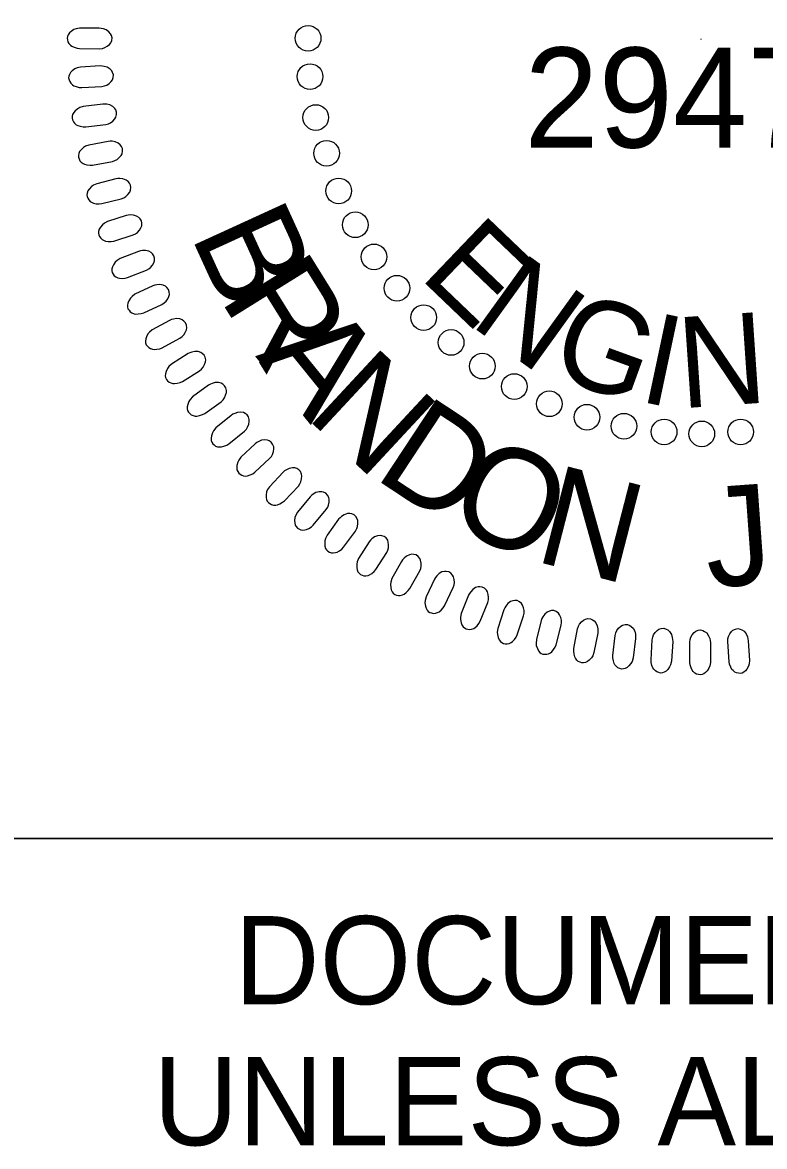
# Model space of a CAD drawing. Extents: x 505602 to 507286, y 483109 to 484209.
# Drawn here: x 507076.9 to 507123.2, y 484026.9 to 484097.1 of the extents above; entities that cross this region are included whole.
import ezdxf

# ---------------------------------------------------------------- set-up
doc = ezdxf.new("R2010")
doc.units = 0
for name, color, linetype in [('Sheet PE Seal Cell', 7, 'Continuous'), ('Sheet Profile CELL', 7, 'Continuous'), ('Sheet Sticker Exception Certification CELL', 7, 'Continuous')]:
    doc.layers.add(name, color=color, linetype=linetype)

msp = doc.modelspace()

# ---------------------------------------------------------------- linework, layer by layer
at = {"layer": 'Sheet PE Seal Cell'}
msp.add_line((507119.206, 484096.054), (507119.206, 484096.007), dxfattribs=at)
for points in [[(507081.659, 484096.717), (507080.432, 484096.717), (507080.213, 484096.679), (507080.073, 484096.628), (507079.904, 484096.516), (507079.794, 484096.418), (507079.714, 484096.306), (507079.674, 484096.202), (507079.654, 484096.089), (507079.674, 484095.978), (507079.704, 484095.858), (507079.763, 484095.753), (507079.864, 484095.649), (507079.943, 484095.589), (507080.093, 484095.521), (507080.273, 484095.462), (507080.432, 484095.439), (507081.689, 484095.431), (507081.858, 484095.453), (507081.998, 484095.499), (507082.157, 484095.588), (507082.297, 484095.7), (507082.377, 484095.797), (507082.437, 484095.954), (507082.457, 484096.104), (507082.416, 484096.253), (507082.367, 484096.358), (507082.268, 484096.485), (507082.098, 484096.605), (507081.918, 484096.672), (507081.789, 484096.702)], [(507081.712, 484094.359), (507080.487, 484094.283), (507080.271, 484094.232), (507080.134, 484094.171), (507079.972, 484094.048), (507079.868, 484093.944), (507079.796, 484093.827), (507079.763, 484093.721), (507079.75, 484093.607), (507079.777, 484093.497), (507079.815, 484093.379), (507079.88, 484093.279), (507079.987, 484093.18), (507080.07, 484093.126), (507080.223, 484093.068), (507080.406, 484093.019), (507080.566, 484093.007), (507081.822, 484093.078), (507081.99, 484093.111), (507082.126, 484093.165), (507082.279, 484093.265), (507082.412, 484093.385), (507082.486, 484093.486), (507082.536, 484093.647), (507082.546, 484093.797), (507082.497, 484093.944), (507082.44, 484094.046), (507082.333, 484094.166), (507082.157, 484094.275), (507081.973, 484094.331), (507081.842, 484094.353)], [(507081.876, 484091.978), (507080.659, 484091.825), (507080.446, 484091.76), (507080.314, 484091.691), (507080.16, 484091.559), (507080.063, 484091.448), (507079.998, 484091.327), (507079.972, 484091.218), (507079.966, 484091.104), (507080, 484090.996), (507080.044, 484090.881), (507080.116, 484090.784), (507080.229, 484090.693), (507080.316, 484090.644), (507080.472, 484090.596), (507080.658, 484090.559), (507080.819, 484090.557), (507082.067, 484090.706), (507082.232, 484090.749), (507082.365, 484090.812), (507082.512, 484090.92), (507082.636, 484091.049), (507082.704, 484091.155), (507082.743, 484091.319), (507082.744, 484091.47), (507082.686, 484091.613), (507082.623, 484091.711), (507082.509, 484091.825), (507082.326, 484091.922), (507082.139, 484091.966), (507082.007, 484091.979)], [(507082.21, 484089.653), (507081.004, 484089.423), (507080.796, 484089.345), (507080.669, 484089.269), (507080.523, 484089.126), (507080.433, 484089.01), (507080.376, 484088.885), (507080.356, 484088.775), (507080.358, 484088.661), (507080.398, 484088.555), (507080.45, 484088.443), (507080.528, 484088.351), (507080.646, 484088.267), (507080.735, 484088.223), (507080.895, 484088.185), (507081.083, 484088.16), (507081.243, 484088.167), (507082.479, 484088.395), (507082.642, 484088.449), (507082.771, 484088.519), (507082.91, 484088.637), (507083.027, 484088.774), (507083.087, 484088.884), (507083.116, 484089.049), (507083.108, 484089.2), (507083.041, 484089.339), (507082.972, 484089.433), (507082.85, 484089.539), (507082.662, 484089.625), (507082.472, 484089.657), (507082.34, 484089.662)], [(507082.689, 484087.312), (507081.501, 484087.007), (507081.298, 484086.916), (507081.175, 484086.831), (507081.039, 484086.68), (507080.957, 484086.559), (507080.907, 484086.43), (507080.895, 484086.319), (507080.903, 484086.205), (507080.95, 484086.102), (507081.009, 484085.994), (507081.093, 484085.907), (507081.216, 484085.831), (507081.308, 484085.792), (507081.469, 484085.764), (507081.658, 484085.751), (507081.818, 484085.769), (507083.037, 484086.073), (507083.196, 484086.137), (507083.32, 484086.216), (507083.452, 484086.342), (507083.56, 484086.485), (507083.613, 484086.599), (507083.632, 484086.766), (507083.614, 484086.916), (507083.538, 484087.051), (507083.464, 484087.14), (507083.336, 484087.239), (507083.142, 484087.312), (507082.951, 484087.333), (507082.818, 484087.329)], [(507083.343, 484085.028), (507082.176, 484084.649), (507081.979, 484084.546), (507081.862, 484084.454), (507081.735, 484084.294), (507081.661, 484084.167), (507081.62, 484084.036), (507081.615, 484083.925), (507081.63, 484083.812), (507081.684, 484083.712), (507081.749, 484083.607), (507081.838, 484083.526), (507081.966, 484083.458), (507082.059, 484083.424), (507082.223, 484083.407), (507082.412, 484083.406), (507082.571, 484083.433), (507083.768, 484083.814), (507083.922, 484083.888), (507084.042, 484083.974), (507084.165, 484084.108), (507084.263, 484084.258), (507084.31, 484084.375), (507084.318, 484084.543), (507084.291, 484084.691), (507084.207, 484084.821), (507084.127, 484084.905), (507083.993, 484084.995), (507083.795, 484085.057), (507083.603, 484085.065), (507083.471, 484085.053)], [(507084.102, 484082.79), (507082.961, 484082.34), (507082.77, 484082.224), (507082.659, 484082.124), (507082.543, 484081.957), (507082.477, 484081.826), (507082.444, 484081.693), (507082.446, 484081.581), (507082.468, 484081.469), (507082.528, 484081.373), (507082.6, 484081.272), (507082.693, 484081.197), (507082.825, 484081.137), (507082.921, 484081.11), (507083.086, 484081.103), (507083.274, 484081.113), (507083.431, 484081.151), (507084.602, 484081.606), (507084.752, 484081.689), (507084.865, 484081.782), (507084.98, 484081.924), (507085.069, 484082.08), (507085.108, 484082.2), (507085.105, 484082.368), (507085.069, 484082.515), (507084.977, 484082.638), (507084.892, 484082.717), (507084.753, 484082.799), (507084.551, 484082.847), (507084.359, 484082.844), (507084.228, 484082.824)], [(507085.001, 484080.631), (507083.891, 484080.109), (507083.709, 484079.982), (507083.604, 484079.875), (507083.499, 484079.701), (507083.441, 484079.567), (507083.416, 484079.431), (507083.425, 484079.32), (507083.454, 484079.21), (507083.52, 484079.117), (507083.598, 484079.021), (507083.697, 484078.952), (507083.832, 484078.9), (507083.929, 484078.88), (507084.093, 484078.882), (507084.281, 484078.905), (507084.435, 484078.952), (507085.576, 484079.48), (507085.719, 484079.573), (507085.827, 484079.673), (507085.932, 484079.821), (507086.012, 484079.982), (507086.043, 484080.105), (507086.03, 484080.272), (507085.984, 484080.416), (507085.884, 484080.534), (507085.794, 484080.608), (507085.651, 484080.681), (507085.446, 484080.716), (507085.255, 484080.701), (507085.125, 484080.673)], [(507086.049, 484078.482), (507084.973, 484077.892), (507084.799, 484077.754), (507084.702, 484077.64), (507084.607, 484077.461), (507084.558, 484077.322), (507084.542, 484077.186), (507084.557, 484077.075), (507084.594, 484076.967), (507084.666, 484076.879), (507084.75, 484076.788), (507084.852, 484076.725), (507084.99, 484076.682), (507085.089, 484076.667), (507085.252, 484076.68), (507085.438, 484076.715), (507085.589, 484076.771), (507086.694, 484077.37), (507086.832, 484077.472), (507086.932, 484077.578), (507087.029, 484077.733), (507087.097, 484077.898), (507087.121, 484078.023), (507087.097, 484078.189), (507087.043, 484078.33), (507086.936, 484078.441), (507086.842, 484078.509), (507086.693, 484078.572), (507086.487, 484078.595), (507086.297, 484078.568), (507086.169, 484078.532)], [(507087.205, 484076.408), (507086.169, 484075.75), (507086.003, 484075.602), (507085.914, 484075.483), (507085.83, 484075.297), (507085.79, 484075.157), (507085.783, 484075.019), (507085.805, 484074.909), (507085.848, 484074.804), (507085.926, 484074.72), (507086.015, 484074.635), (507086.121, 484074.579), (507086.261, 484074.544), (507086.36, 484074.536), (507086.523, 484074.559), (507086.707, 484074.605), (507086.853, 484074.671), (507087.919, 484075.338), (507088.05, 484075.447), (507088.144, 484075.561), (507088.23, 484075.721), (507088.288, 484075.891), (507088.304, 484076.016), (507088.27, 484076.181), (507088.207, 484076.318), (507088.093, 484076.422), (507087.995, 484076.484), (507087.842, 484076.538), (507087.635, 484076.548), (507087.447, 484076.509), (507087.322, 484076.464)], [(507088.482, 484074.433), (507087.488, 484073.712), (507087.333, 484073.553), (507087.25, 484073.429), (507087.179, 484073.238), (507087.148, 484073.095), (507087.149, 484072.957), (507087.178, 484072.85), (507087.228, 484072.746), (507087.31, 484072.668), (507087.405, 484072.589), (507087.515, 484072.539), (507087.657, 484072.513), (507087.756, 484072.512), (507087.917, 484072.545), (507088.097, 484072.602), (507088.24, 484072.677), (507089.261, 484073.41), (507089.385, 484073.528), (507089.471, 484073.646), (507089.548, 484073.812), (507089.595, 484073.985), (507089.603, 484074.11), (507089.559, 484074.273), (507089.487, 484074.406), (507089.367, 484074.503), (507089.265, 484074.558), (507089.11, 484074.603), (507088.903, 484074.6), (507088.717, 484074.549), (507088.595, 484074.497)], [(507089.885, 484072.551), (507088.939, 484071.769), (507088.794, 484071.601), (507088.72, 484071.472), (507088.661, 484071.278), (507088.638, 484071.133), (507088.648, 484070.996), (507088.684, 484070.89), (507088.74, 484070.79), (507088.827, 484070.717), (507088.926, 484070.644), (507089.039, 484070.601), (507089.182, 484070.584), (507089.282, 484070.589), (507089.44, 484070.632), (507089.616, 484070.701), (507089.754, 484070.784), (507090.727, 484071.58), (507090.844, 484071.705), (507090.922, 484071.829), (507090.988, 484071.999), (507091.025, 484072.175), (507091.024, 484072.3), (507090.97, 484072.46), (507090.89, 484072.587), (507090.764, 484072.677), (507090.659, 484072.726), (507090.501, 484072.761), (507090.295, 484072.745), (507090.113, 484072.682), (507089.994, 484072.623)], [(507091.395, 484070.781), (507090.5, 484069.941), (507090.366, 484069.764), (507090.3, 484069.631), (507090.253, 484069.433), (507090.24, 484069.287), (507090.258, 484069.15), (507090.301, 484069.046), (507090.363, 484068.951), (507090.454, 484068.883), (507090.558, 484068.816), (507090.673, 484068.781), (507090.818, 484068.773), (507090.916, 484068.784), (507091.072, 484068.837), (507091.244, 484068.916), (507091.375, 484069.009), (507092.296, 484069.864), (507092.405, 484069.996), (507092.476, 484070.125), (507092.531, 484070.299), (507092.556, 484070.476), (507092.548, 484070.601), (507092.484, 484070.758), (507092.396, 484070.88), (507092.265, 484070.961), (507092.157, 484071.004), (507091.997, 484071.028), (507091.792, 484070.999), (507091.614, 484070.925), (507091.5, 484070.858)], [(507093.131, 484069.003), (507092.29, 484068.108), (507092.167, 484067.923), (507092.11, 484067.786), (507092.075, 484067.585), (507092.071, 484067.438), (507092.098, 484067.304), (507092.147, 484067.204), (507092.215, 484067.112), (507092.31, 484067.05), (507092.419, 484066.99), (507092.535, 484066.961), (507092.68, 484066.963), (507092.778, 484066.979), (507092.93, 484067.042), (507093.096, 484067.132), (507093.222, 484067.233), (507094.088, 484068.144), (507094.187, 484068.283), (507094.25, 484068.416), (507094.294, 484068.593), (507094.308, 484068.771), (507094.292, 484068.896), (507094.219, 484069.047), (507094.123, 484069.165), (507093.987, 484069.238), (507093.876, 484069.273), (507093.716, 484069.288), (507093.513, 484069.245), (507093.34, 484069.161), (507093.23, 484069.087)], [(507094.821, 484067.473), (507094.038, 484066.527), (507093.927, 484066.334), (507093.878, 484066.194), (507093.856, 484065.992), (507093.862, 484065.845), (507093.897, 484065.712), (507093.952, 484065.614), (507094.026, 484065.527), (507094.124, 484065.472), (507094.236, 484065.419), (507094.354, 484065.398), (507094.499, 484065.408), (507094.596, 484065.431), (507094.743, 484065.503), (507094.903, 484065.603), (507095.023, 484065.712), (507095.83, 484066.676), (507095.921, 484066.82), (507095.974, 484066.957), (507096.008, 484067.137), (507096.011, 484067.315), (507095.986, 484067.44), (507095.903, 484067.585), (507095.801, 484067.696), (507095.661, 484067.76), (507095.547, 484067.789), (507095.386, 484067.793), (507095.187, 484067.739), (507095.019, 484067.643), (507094.914, 484067.563)], [(507096.601, 484066.072), (507095.88, 484065.079), (507095.781, 484064.88), (507095.741, 484064.736), (507095.732, 484064.533), (507095.747, 484064.387), (507095.79, 484064.257), (507095.851, 484064.163), (507095.93, 484064.081), (507096.033, 484064.031), (507096.148, 484063.985), (507096.267, 484063.972), (507096.41, 484063.991), (507096.506, 484064.02), (507096.648, 484064.102), (507096.802, 484064.212), (507096.914, 484064.328), (507097.659, 484065.34), (507097.74, 484065.49), (507097.786, 484065.63), (507097.808, 484065.811), (507097.8, 484065.99), (507097.767, 484066.111), (507097.676, 484066.253), (507097.566, 484066.357), (507097.422, 484066.412), (507097.308, 484066.433), (507097.147, 484066.428), (507096.95, 484066.36), (507096.79, 484066.255), (507096.69, 484066.167)], [(507098.503, 484064.659), (507097.846, 484063.623), (507097.759, 484063.418), (507097.728, 484063.272), (507097.732, 484063.068), (507097.756, 484062.924), (507097.808, 484062.797), (507097.874, 484062.706), (507097.959, 484062.63), (507098.063, 484062.586), (507098.181, 484062.547), (507098.301, 484062.542), (507098.443, 484062.57), (507098.536, 484062.606), (507098.673, 484062.695), (507098.82, 484062.815), (507098.924, 484062.938), (507099.604, 484063.994), (507099.676, 484064.15), (507099.713, 484064.292), (507099.723, 484064.474), (507099.703, 484064.652), (507099.663, 484064.772), (507099.564, 484064.907), (507099.448, 484065.003), (507099.3, 484065.05), (507099.185, 484065.064), (507099.025, 484065.048), (507098.833, 484064.969), (507098.679, 484064.853), (507098.585, 484064.76)], [(507100.521, 484063.443), (507099.93, 484062.369), (507099.857, 484062.158), (507099.835, 484062.011), (507099.852, 484061.808), (507099.884, 484061.665), (507099.944, 484061.541), (507100.016, 484061.456), (507100.105, 484061.384), (507100.212, 484061.348), (507100.332, 484061.316), (507100.452, 484061.318), (507100.592, 484061.355), (507100.683, 484061.396), (507100.814, 484061.495), (507100.953, 484061.623), (507101.05, 484061.752), (507101.662, 484062.85), (507101.723, 484063.009), (507101.751, 484063.153), (507101.75, 484063.336), (507101.72, 484063.512), (507101.673, 484063.629), (507101.564, 484063.757), (507101.442, 484063.847), (507101.292, 484063.884), (507101.176, 484063.891), (507101.017, 484063.865), (507100.831, 484063.773), (507100.685, 484063.649), (507100.596, 484063.55)], [(507102.58, 484062.337), (507102.058, 484061.227), (507101.998, 484061.013), (507101.986, 484060.864), (507102.015, 484060.662), (507102.056, 484060.522), (507102.124, 484060.402), (507102.201, 484060.321), (507102.295, 484060.256), (507102.404, 484060.226), (507102.525, 484060.202), (507102.645, 484060.212), (507102.783, 484060.257), (507102.871, 484060.304), (507102.995, 484060.41), (507103.126, 484060.547), (507103.215, 484060.682), (507103.757, 484061.816), (507103.808, 484061.979), (507103.827, 484062.124), (507103.814, 484062.307), (507103.773, 484062.481), (507103.718, 484062.595), (507103.602, 484062.715), (507103.474, 484062.798), (507103.323, 484062.825), (507103.206, 484062.824), (507103.049, 484062.789), (507102.869, 484062.686), (507102.732, 484062.552), (507102.65, 484062.448)], [(507104.708, 484061.329), (507104.256, 484060.188), (507104.21, 484059.97), (507104.207, 484059.821), (507104.249, 484059.622), (507104.298, 484059.484), (507104.374, 484059.369), (507104.456, 484059.293), (507104.553, 484059.233), (507104.664, 484059.211), (507104.787, 484059.195), (507104.906, 484059.211), (507105.04, 484059.266), (507105.125, 484059.318), (507105.243, 484059.432), (507105.364, 484059.577), (507105.444, 484059.717), (507105.914, 484060.883), (507105.956, 484061.048), (507105.965, 484061.194), (507105.941, 484061.376), (507105.888, 484061.547), (507105.827, 484061.657), (507105.703, 484061.771), (507105.571, 484061.844), (507105.418, 484061.862), (507105.302, 484061.854), (507105.147, 484061.809), (507104.974, 484061.695), (507104.845, 484061.552), (507104.77, 484061.443)], [(507106.917, 484060.426), (507106.537, 484059.26), (507106.505, 484059.039), (507106.511, 484058.891), (507106.565, 484058.694), (507106.624, 484058.56), (507106.706, 484058.45), (507106.793, 484058.38), (507106.894, 484058.326), (507107.006, 484058.31), (507107.13, 484058.302), (507107.247, 484058.326), (507107.378, 484058.389), (507107.459, 484058.446), (507107.57, 484058.568), (507107.682, 484058.72), (507107.753, 484058.864), (507108.149, 484060.057), (507108.18, 484060.225), (507108.18, 484060.372), (507108.144, 484060.551), (507108.081, 484060.719), (507108.013, 484060.825), (507107.882, 484060.93), (507107.746, 484060.996), (507107.592, 484061.004), (507107.477, 484060.988), (507107.325, 484060.933), (507107.159, 484060.809), (507107.039, 484060.659), (507106.971, 484060.545)], [(507109.25, 484059.753), (507108.944, 484058.565), (507108.926, 484058.344), (507108.941, 484058.195), (507109.008, 484058.003), (507109.074, 484057.872), (507109.164, 484057.768), (507109.255, 484057.703), (507109.358, 484057.655), (507109.472, 484057.647), (507109.595, 484057.647), (507109.711, 484057.678), (507109.837, 484057.749), (507109.915, 484057.81), (507110.018, 484057.939), (507110.12, 484058.098), (507110.182, 484058.247), (507110.502, 484059.462), (507110.522, 484059.632), (507110.513, 484059.778), (507110.466, 484059.955), (507110.393, 484060.118), (507110.318, 484060.22), (507110.181, 484060.317), (507110.042, 484060.373), (507109.886, 484060.372), (507109.773, 484060.35), (507109.625, 484060.285), (507109.467, 484060.15), (507109.357, 484059.993), (507109.296, 484059.875)], [(507112.772, 484058.966), (507112.541, 484057.761), (507112.463, 484057.552), (507112.386, 484057.425), (507112.244, 484057.279), (507112.128, 484057.19), (507112.003, 484057.133), (507111.892, 484057.113), (507111.778, 484057.115), (507111.673, 484057.155), (507111.56, 484057.207), (507111.469, 484057.285), (507111.385, 484057.403), (507111.341, 484057.493), (507111.303, 484057.652), (507111.278, 484057.84), (507111.286, 484058.001), (507111.514, 484059.236), (507111.568, 484059.399), (507111.639, 484059.527), (507111.757, 484059.667), (507111.893, 484059.783), (507112.003, 484059.844), (507112.168, 484059.873), (507112.32, 484059.864), (507112.458, 484059.797), (507112.552, 484059.728), (507112.658, 484059.607), (507112.743, 484059.418), (507112.776, 484059.228), (507112.781, 484059.096)], [(507115.138, 484058.64), (507114.983, 484057.423), (507114.919, 484057.21), (507114.849, 484057.077), (507114.717, 484056.923), (507114.607, 484056.827), (507114.485, 484056.761), (507114.377, 484056.735), (507114.263, 484056.73), (507114.155, 484056.764), (507114.039, 484056.808), (507113.943, 484056.88), (507113.852, 484056.993), (507113.802, 484057.08), (507113.754, 484057.237), (507113.718, 484057.422), (507113.715, 484057.583), (507113.866, 484058.83), (507113.909, 484058.996), (507113.972, 484059.129), (507114.08, 484059.276), (507114.209, 484059.401), (507114.316, 484059.467), (507114.479, 484059.507), (507114.63, 484059.508), (507114.773, 484059.449), (507114.871, 484059.387), (507114.985, 484059.272), (507115.081, 484059.089), (507115.126, 484058.902), (507115.139, 484058.77)], [(507117.455, 484058.442), (507117.377, 484057.218), (507117.326, 484057.002), (507117.265, 484056.865), (507117.143, 484056.703), (507117.039, 484056.599), (507116.922, 484056.527), (507116.815, 484056.493), (507116.701, 484056.481), (507116.591, 484056.509), (507116.474, 484056.545), (507116.373, 484056.611), (507116.275, 484056.718), (507116.22, 484056.801), (507116.162, 484056.955), (507116.114, 484057.138), (507116.102, 484057.299), (507116.173, 484058.553), (507116.207, 484058.721), (507116.261, 484058.857), (507116.36, 484059.011), (507116.48, 484059.143), (507116.583, 484059.217), (507116.743, 484059.266), (507116.894, 484059.277), (507117.041, 484059.227), (507117.141, 484059.171), (507117.262, 484059.064), (507117.37, 484058.887), (507117.427, 484058.703), (507117.448, 484058.573)], [(507119.808, 484058.37), (507119.808, 484057.143), (507119.77, 484056.925), (507119.718, 484056.784), (507119.606, 484056.615), (507119.508, 484056.505), (507119.396, 484056.425), (507119.292, 484056.386), (507119.18, 484056.366), (507119.068, 484056.386), (507118.948, 484056.416), (507118.843, 484056.475), (507118.738, 484056.576), (507118.679, 484056.655), (507118.611, 484056.805), (507118.552, 484056.984), (507118.529, 484057.144), (507118.522, 484058.4), (507118.545, 484058.57), (507118.59, 484058.71), (507118.679, 484058.869), (507118.791, 484059.009), (507118.889, 484059.089), (507119.046, 484059.148), (507119.196, 484059.168), (507119.345, 484059.128), (507119.45, 484059.078), (507119.577, 484058.979), (507119.696, 484058.809), (507119.764, 484058.629), (507119.793, 484058.5)], [(507122.175, 484058.493), (507122.251, 484057.268), (507122.228, 484057.047), (507122.185, 484056.904), (507122.083, 484056.728), (507121.994, 484056.612), (507121.886, 484056.526), (507121.785, 484056.48), (507121.674, 484056.453), (507121.561, 484056.466), (507121.44, 484056.488), (507121.331, 484056.541), (507121.22, 484056.635), (507121.156, 484056.71), (507121.08, 484056.856), (507121.009, 484057.031), (507120.976, 484057.189), (507120.89, 484058.442), (507120.902, 484058.613), (507120.938, 484058.755), (507121.018, 484058.92), (507121.121, 484059.066), (507121.213, 484059.152), (507121.366, 484059.222), (507121.514, 484059.251), (507121.665, 484059.22), (507121.773, 484059.177), (507121.906, 484059.086), (507122.036, 484058.924), (507122.115, 484058.748), (507122.153, 484058.621)]]:
    msp.add_lwpolyline(points, close=True, dxfattribs=at)
for centre in [(507094.698, 484096.081), (507094.817, 484093.691), (507095.174, 484091.141), (507095.85, 484088.91), (507096.606, 484086.559), (507097.641, 484084.448), (507098.81, 484082.444), (507100.242, 484080.491), (507101.914, 484078.658), (507103.625, 484077.104), (507105.576, 484075.63), (507107.566, 484074.354), (507109.755, 484073.278), (507112.104, 484072.44), (507114.413, 484071.882), (507116.921, 484071.523), (507119.27, 484071.402), (507121.699, 484071.521)]:
    msp.add_circle(centre, 0.801, dxfattribs=at)
at = {"layer": 'Sheet Profile CELL'}
msp.add_lwpolyline([(507069.03, 484158.662), (507169.08, 484158.662), (507169.08, 484046.162), (507069.03, 484046.162)], close=True, dxfattribs=at)
at = {"layer": 'Sheet Sticker Exception Certification CELL'}
msp.add_line((507069.03, 484046.162), (507269.067, 484046.162), dxfattribs=at)
msp.add_line((507069.03, 484046.162), (507269.067, 484046.162), dxfattribs=at)

# ---------------------------------------------------------------- texts
at = {"layer": 'Sheet PE Seal Cell'}
for s, height, rotation, p in [('29470', 6.2363, 359.98136, (507108.193, 484089.269)), ('B', 6.236, 294.5897, (507087.323, 484083.831)), ('E', 5.669, 316.26559, (507101.563, 484081.209)), ('R', 6.236, 301.86473, (507089.134, 484079.874)), ('N', 5.669, 324.20538, (507104.698, 484078.254)), ('G', 5.669, 340.08498, (507109.592, 484075.156)), ('I', 5.669, 348.02477, (507115.221, 484073.466)), ('N', 5.669, 3.90437, (507117.974, 484072.994)), ('A', 6.236, 308.98157, (507091.377, 484076.256)), ('N', 6.236, 317.09274, (507094.456, 484072.508)), ('D', 6.236, 326.58243, (507098.686, 484068.727)), ('O', 6.236, 335.45066, (507103.152, 484065.869)), ('N', 6.236, 345.5505, (507108.704, 484063.497)), ('J', 6.236, 4.1457, (507119.655, 484061.805))]:
    msp.add_text(s, height=height, rotation=rotation, dxfattribs=at).set_placement(p)
at = {"layer": 'Sheet Sticker Exception Certification CELL'}
for s, p in [('DOCUMENT NOT CONSIDERED FINAL', (507090.101, 484035.816)), ('DOCUMENT NOT CONSIDERED FINAL', (507090.101, 484035.816)), ('UNLESS ALL SIGNATURES COMPLETED', (507085.03, 484027.016)), ('UNLESS ALL SIGNATURES COMPLETED', (507085.03, 484027.016))]:
    msp.add_text(s, height=5.5, dxfattribs=at).set_placement(p)

doc.saveas('drawing.dxf')
